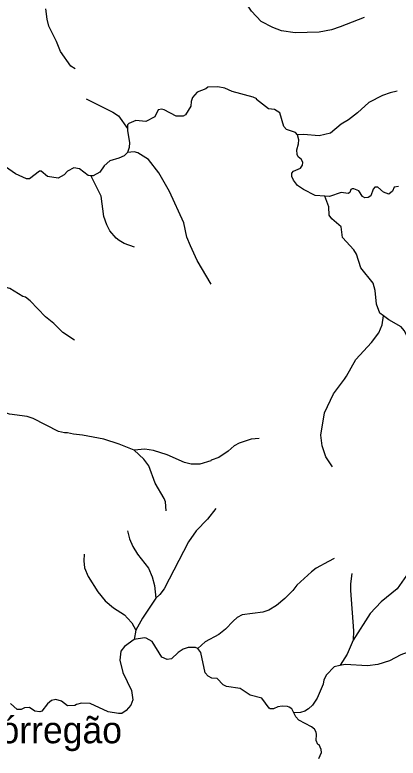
# Model space of a CAD drawing. Extents: x 393 to 446.6, y 8175.5 to 8231.
# Drawn here: x 412.63 to 415.52, y 8185.27 to 8190.87 of the extents above; entities that cross this region are included whole.
import ezdxf
from ezdxf.enums import TextEntityAlignment as Align

# ---------------------------------------------------------------- set-up
doc = ezdxf.new("R2010")
doc.units = 0
doc.header["$LTSCALE"] = 0.064
doc.linetypes.add('LONG_DASHED', pattern=[7.5, 6, -1.5])
doc.layers.add('61', color=7, linetype='Continuous')
doc.layers.add('7', color=7, linetype='Continuous', lineweight=25)
doc.layers.add('9', color=7, linetype='LONG_DASHED', lineweight=25)

msp = doc.modelspace()

# ---------------------------------------------------------------- linework, layer by layer
at = {"layer": '7'}
msp.add_line((413.5401, 8186.2317), (413.5276, 8186.1617), dxfattribs=at)
for points in [[(415.2604, 8190.8482), (415.0787, 8190.776), (415.0141, 8190.7551), (414.9204, 8190.7373), (414.7396, 8190.7308), (414.6362, 8190.747), (414.5716, 8190.7712), (414.4844, 8190.818), (414.4117, 8190.8955), (414.3294, 8191.0215), (414.3067, 8191.0474), (414.205, 8191.1313), (414.1092, 8191.1682)], [(413.083, 8190.4603), (413.0504, 8190.4801), (412.9729, 8190.592), (412.9439, 8190.6663), (412.8857, 8190.7825), (412.8712, 8190.8342), (412.8633, 8190.9113)], [(413.0772, 8188.4153), (412.9907, 8188.4734), (412.9229, 8188.5412), (412.8599, 8188.5912), (412.7436, 8188.7124), (412.7081, 8188.7398), (412.6888, 8188.7446), (412.5919, 8188.8044), (412.5628, 8188.8141), (412.4788, 8188.8157), (412.3626, 8188.7963), (412.2851, 8188.7947), (412.2398, 8188.7995), (412.1432, 8188.83), (412.1222, 8188.83), (412.1106, 8188.8205)], [(413.5273, 8187.5871), (413.4138, 8187.6337), (413.2992, 8187.6692), (413.1377, 8187.7015), (413.0699, 8187.7079), (413.0246, 8187.7192), (413.002, 8187.7176), (412.9568, 8187.7289), (412.7663, 8187.8258), (412.721, 8187.8403), (412.5886, 8187.8597), (412.4816, 8187.8904), (412.4223, 8187.9324), (412.3835, 8187.9728), (412.3674, 8188.0115), (412.3416, 8188.1545)], [(414.4679, 8187.6765), (414.4101, 8187.6708), (414.3197, 8187.6401), (414.2809, 8187.6191), (414.2357, 8187.5803), (414.1647, 8187.5319), (414.1066, 8187.5126), (414.1049, 8187.5061), (414.0226, 8187.4819), (413.958, 8187.4819), (413.9063, 8187.4948), (413.7771, 8187.5513), (413.6738, 8187.5852), (413.6092, 8187.5949), (413.5273, 8187.5871)], [(413.7699, 8187.1302), (413.7642, 8187.1977), (413.7545, 8187.2235), (413.6867, 8187.3398), (413.6382, 8187.469), (413.6011, 8187.519), (413.5273, 8187.5871)], [(414.1429, 8187.1477), (414.0791, 8187.0685), (413.9951, 8186.9797), (413.937, 8186.8973), (413.7529, 8186.5437), (413.7222, 8186.5001), (413.692, 8186.4727)], [(413.4785, 8186.9788), (413.4929, 8186.9199), (413.5171, 8186.8618), (413.5527, 8186.8036), (413.635, 8186.6971), (413.6641, 8186.6325), (413.6802, 8186.5679), (413.692, 8186.4727)], [(413.1515, 8186.8028), (413.148, 8186.7528), (413.1538, 8186.7003), (413.1812, 8186.6357), (413.2539, 8186.5195), (413.3088, 8186.4516), (413.3718, 8186.3999), (413.4542, 8186.3466), (413.4784, 8186.3225), (413.509, 8186.2869), (413.5401, 8186.2317)], [(415.0341, 8186.7724), (414.9918, 8186.749), (414.8978, 8186.6971), (414.8623, 8186.6712), (414.754, 8186.5711), (414.7218, 8186.5291), (414.662, 8186.4694), (414.599, 8186.4161), (414.5425, 8186.3822), (414.4973, 8186.366), (414.3407, 8186.3466), (414.3036, 8186.3257), (414.2729, 8186.2998), (414.2147, 8186.2385), (414.1663, 8186.1981), (414.0629, 8186.1432), (414.0071, 8186.0933)], [(415.6246, 8186.7521), (415.5792, 8186.6422), (415.5082, 8186.5421), (415.3887, 8186.4435), (415.3063, 8186.358), (415.1773, 8186.1552)], [(415.168, 8186.6578), (415.1561, 8186.5808), (415.1561, 8186.5292), (415.1803, 8186.2256), (415.1773, 8186.1552)], [(413.692, 8186.4727), (413.6699, 8186.4424), (413.5914, 8186.3225), (413.5401, 8186.2317)], [(415.9215, 8186.4638), (415.8731, 8186.3709), (415.8473, 8186.2934), (415.8021, 8186.203), (415.7649, 8186.1561), (415.7246, 8186.1238), (415.6664, 8186.0931), (415.5373, 8186.0463), (415.4501, 8186.0011), (415.3629, 8185.972), (415.2854, 8185.9623), (415.1174, 8185.972), (415.0765, 8185.964)], [(414.0071, 8186.0933), (413.9908, 8186.1014), (413.9354, 8186.1012), (413.8966, 8186.0883), (413.8579, 8186.0641), (413.8094, 8186.0156), (413.7755, 8186.0092), (413.7351, 8186.0285), (413.6641, 8186.1464), (413.6189, 8186.1706), (413.606, 8186.1739), (413.5276, 8186.1617)], [(413.5276, 8186.1617), (413.4557, 8186.1093), (413.4283, 8186.0738), (413.4186, 8186.006), (413.4428, 8185.9123), (413.5074, 8185.7767), (413.5187, 8185.7056), (413.5026, 8185.6652), (413.4671, 8185.6248), (413.4348, 8185.6038), (413.409, 8185.6022), (413.3315, 8185.6152), (413.1958, 8185.6781), (413.1312, 8185.6814), (413.0925, 8185.6717), (413.0811, 8185.6636), (413.0246, 8185.662), (412.9794, 8185.6975), (412.9374, 8185.7088), (412.9051, 8185.7008), (412.8761, 8185.6765), (412.8324, 8185.6216), (412.8179, 8185.6152), (412.7792, 8185.6216), (412.7404, 8185.6475), (412.7017, 8185.6458), (412.6758, 8185.6329), (412.6468, 8185.6329), (412.5967, 8185.6797)], [(415.1773, 8186.1552), (415.1319, 8186.0512), (415.0787, 8185.9675), (415.0765, 8185.964)], [(414.7296, 8185.6093), (414.7153, 8185.6394), (414.6943, 8185.6507), (414.6814, 8185.6571), (414.6427, 8185.6587), (414.6087, 8185.6539), (414.5781, 8185.6394), (414.5522, 8185.6394), (414.5441, 8185.6426), (414.4892, 8185.7201), (414.4004, 8185.7411), (414.3262, 8185.7928), (414.2228, 8185.8057), (414.1986, 8185.8203), (414.1534, 8185.8671), (414.113, 8185.8703), (414.0839, 8185.8848), (414.0629, 8185.9107), (414.029, 8186.0641), (414.0071, 8186.0933)], [(415.0765, 8185.964), (415.035, 8185.9559), (414.9753, 8185.8945), (414.9559, 8185.8574), (414.951, 8185.8251), (414.9058, 8185.7185), (414.8703, 8185.6669), (414.8412, 8185.6378), (414.8138, 8185.6216), (414.7815, 8185.6119), (414.7333, 8185.6095), (414.7296, 8185.6093)], [(414.9187, 8185.2632), (414.9381, 8185.3084), (414.9365, 8185.331), (414.9204, 8185.3681), (414.9107, 8185.3697), (414.8978, 8185.3988), (414.901, 8185.444), (414.8978, 8185.4634), (414.8849, 8185.486), (414.8622, 8185.5038), (414.7686, 8185.5538), (414.7444, 8185.578), (414.7296, 8185.6093)]]:
    msp.add_lwpolyline(points, dxfattribs=at)
at = {"layer": '9'}
for points in [[(414.7587, 8189.9638), (414.7424, 8189.9801), (414.6759, 8190.0046), (414.656, 8190.0268), (414.6257, 8190.1294), (414.5854, 8190.1545), (414.5387, 8190.1603), (414.4494, 8190.2297), (414.4521, 8190.2351), (414.423, 8190.248), (414.2648, 8190.29), (414.2115, 8190.3158), (414.1582, 8190.3239), (414.0823, 8190.3223), (414.0662, 8190.3094), (414.0015, 8190.2852), (413.9676, 8190.2448), (413.9563, 8190.2141), (413.9548, 8190.1802), (413.9144, 8190.114), (413.8966, 8190.1043), (413.845, 8190.1027), (413.7545, 8190.1511), (413.7351, 8190.156), (413.7093, 8190.1511), (413.6835, 8190.0995), (413.6157, 8190.0639), (413.5397, 8190.072), (413.4864, 8190.0478), (413.4784, 8190.0397), (413.478, 8190.0115)], [(415.5085, 8190.291), (415.4549, 8190.2803), (415.3984, 8190.2593), (415.295, 8190.206), (415.2094, 8190.1285), (415.1416, 8190.0768), (415.0867, 8190.0446), (415.0076, 8189.9767), (414.9204, 8189.9557), (414.8041, 8189.9654), (414.7587, 8189.9638)], [(413.1652, 8190.2348), (413.367, 8190.135), (413.4106, 8190.1075), (413.4778, 8190.0118), (413.478, 8190.0115)], [(413.478, 8190.0115), (413.4778, 8189.9936), (413.493, 8189.905), (413.4907, 8189.8688), (413.4766, 8189.8303)], [(414.9625, 8189.5013), (414.8913, 8189.5052), (414.8025, 8189.5504), (414.7573, 8189.5827), (414.7267, 8189.6226), (414.7162, 8189.6494), (414.7162, 8189.6751), (414.7267, 8189.6903), (414.7792, 8189.7124), (414.7944, 8189.7357), (414.7979, 8189.7556), (414.7874, 8189.7766), (414.7629, 8189.7987), (414.7547, 8189.8151), (414.7524, 8189.8512), (414.7664, 8189.8944), (414.7675, 8189.9259), (414.7587, 8189.9638)], [(413.4766, 8189.8303), (413.4525, 8189.8055), (413.4122, 8189.7862), (413.3443, 8189.7684), (413.3007, 8189.7297), (413.2685, 8189.6828), (413.2178, 8189.6543), (413.201, 8189.6554)], [(414.107, 8188.8382), (414.0032, 8189.0175), (413.9515, 8189.1257), (413.9241, 8189.1919), (413.9013, 8189.301), (413.7949, 8189.5359), (413.7141, 8189.6764), (413.6366, 8189.7765), (413.5543, 8189.8265), (413.5275, 8189.8362), (413.4766, 8189.8303)], [(413.201, 8189.6554), (413.1816, 8189.6566), (413.1151, 8189.7068), (413.0731, 8189.715), (413.0246, 8189.6899), (413.0004, 8189.6618), (412.9552, 8189.6376), (412.8761, 8189.6505), (412.826, 8189.6893), (412.8147, 8189.6893), (412.7404, 8189.6311), (412.7178, 8189.6311), (412.6339, 8189.6683), (412.5144, 8189.7522), (412.4884, 8189.7544)], [(413.5306, 8189.116), (413.4525, 8189.1451), (413.4154, 8189.1677), (413.3912, 8189.1839), (413.3443, 8189.2404), (413.3217, 8189.284), (413.2991, 8189.3486), (413.2781, 8189.5004), (413.2027, 8189.652), (413.201, 8189.6554)], [(415.5179, 8189.573), (415.486, 8189.5685), (415.4732, 8189.5393), (415.4463, 8189.5172), (415.4055, 8189.5323), (415.3623, 8189.5685), (415.3407, 8189.5691), (415.3278, 8189.5539), (415.3103, 8189.5026), (415.2905, 8189.4921), (415.266, 8189.4886), (415.2485, 8189.4979), (415.2193, 8189.5411), (415.1813, 8189.5557), (415.1685, 8189.5568), (415.1603, 8189.551), (415.1522, 8189.5289), (415.1382, 8189.5219), (415.0868, 8189.5289), (414.9998, 8189.4992), (414.9625, 8189.5013)], [(415.4045, 8188.5995), (415.3767, 8188.6206), (415.3532, 8188.6881), (415.3418, 8188.7899), (415.3289, 8188.8464), (415.2352, 8188.961), (415.2013, 8189.0644), (415.182, 8189.0967), (415.098, 8189.1903), (415.0867, 8189.2695), (415.0173, 8189.3292), (414.9963, 8189.3583), (414.9929, 8189.4219), (414.9625, 8189.5013)], [(415.0209, 8187.462), (414.9705, 8187.5384), (414.943, 8187.6208), (414.9333, 8187.6999), (414.9624, 8187.8678), (415.0286, 8188.0115), (415.1126, 8188.1229), (415.1258, 8188.1456), (415.1981, 8188.2699), (415.3144, 8188.3974), (415.3709, 8188.4717), (415.3951, 8188.5315), (415.4045, 8188.5995)], [(415.9311, 8188.0253), (415.8564, 8188.0823), (415.8471, 8188.0894), (415.6906, 8188.1665), (415.6519, 8188.2118), (415.6325, 8188.2505), (415.6099, 8188.3313), (415.5986, 8188.4168), (415.5614, 8188.4895), (415.5388, 8188.517), (415.4452, 8188.5686), (415.4045, 8188.5995)]]:
    msp.add_lwpolyline(points, dxfattribs=at)

# ---------------------------------------------------------------- texts
at = {"layer": '61'}
msp.add_text('Córregão', height=0.2, dxfattribs=at).set_placement((412.8784, 8185.379), align=Align.CENTER)

doc.saveas('drawing.dxf')
